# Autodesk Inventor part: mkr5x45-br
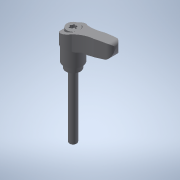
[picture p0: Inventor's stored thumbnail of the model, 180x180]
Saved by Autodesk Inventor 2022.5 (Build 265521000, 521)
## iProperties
Created: 2017-09
Part Number: mkr5x45-br
Material: 一般
Document SubType Name: Modeling
Designer: imaocorp
Density: 1 g/cm^3
Appearance: 既定
Author: imaocorp
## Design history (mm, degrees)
node "mkr5x45-br.x_t1"
node "mkr5x45-br"
node "Base1"
